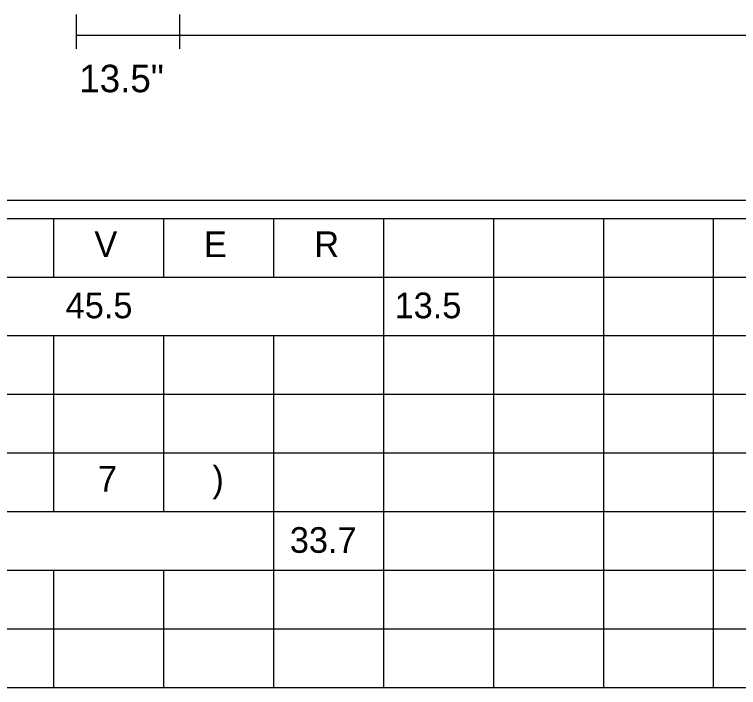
# Model space of a CAD drawing. Extents: x 10268312 to 10268471, y 2141099 to 2141204.
# Drawn here: x 10268380.92 to 10268400.67, y 2141160.23 to 2141178.59 of the extents above; entities that cross this region are included whole.
import ezdxf

# ---------------------------------------------------------------- set-up
doc = ezdxf.new("R2010")
doc.units = 0
for name, color, linetype in [('GSDims', 7, 'Continuous'), ('SumBoxLines_dp', 7, 'Continuous'), ('SumBoxLinesMin_dp', 7, 'Continuous'), ('TextLabel', 7, 'Continuous')]:
    doc.layers.add(name, color=color, linetype=linetype)

msp = doc.modelspace()

# ---------------------------------------------------------------- linework, layer by layer
at = {"layer": 'GSDims'}
for p, q in [((10268382.605, 2141178.591), (10268382.605, 2141177.653)), ((10268385.418, 2141178.591), (10268385.418, 2141177.653)), ((10268385.418, 2141178.591), (10268385.418, 2141177.653)), ((10268382.605, 2141178.028), (10268385.418, 2141178.028)), ((10268385.418, 2141178.028), (10268427.293, 2141178.028))]:
    msp.add_line(p, q, dxfattribs=at)
at = {"layer": 'SumBoxLines_dp'}
for p, q in [((10268341.73, 2141173.528), (10268470.98, 2141173.528)), ((10268318.48, 2141173.028), (10268470.98, 2141173.028)), ((10268381.98, 2141173.028), (10268381.98, 2141171.428)), ((10268384.98, 2141173.028), (10268384.98, 2141171.428)), ((10268387.98, 2141173.028), (10268387.98, 2141171.428)), ((10268390.98, 2141173.028), (10268390.98, 2141170.642)), ((10268393.98, 2141173.028), (10268393.98, 2141160.228)), ((10268396.98, 2141173.028), (10268396.98, 2141163.428)), ((10268399.98, 2141173.028), (10268399.98, 2141160.228)), ((10268390.98, 2141170.642), (10268390.98, 2141160.228)), ((10268318.48, 2141169.828), (10268470.98, 2141169.828)), ((10268381.98, 2141169.828), (10268381.98, 2141165.028)), ((10268384.98, 2141169.828), (10268384.98, 2141165.028)), ((10268387.98, 2141169.828), (10268387.98, 2141160.228)), ((10268318.48, 2141166.628), (10268470.98, 2141166.628)), ((10268318.48, 2141163.428), (10268470.98, 2141163.428)), ((10268381.98, 2141163.428), (10268381.98, 2141160.228)), ((10268384.98, 2141163.428), (10268384.98, 2141160.228)), ((10268396.98, 2141163.428), (10268396.98, 2141160.228)), ((10268318.48, 2141160.228), (10268470.98, 2141160.228))]:
    msp.add_line(p, q, dxfattribs=at)
at = {"layer": 'SumBoxLinesMin_dp'}
for p, q in [((10268318.48, 2141171.428), (10268470.98, 2141171.428)), ((10268318.48, 2141168.228), (10268470.98, 2141168.228)), ((10268318.48, 2141165.028), (10268470.98, 2141165.028)), ((10268318.48, 2141161.828), (10268470.98, 2141161.828))]:
    msp.add_line(p, q, dxfattribs=at)

# ---------------------------------------------------------------- texts
at = {"layer": 'GSDims'}
msp.add_text('13.5"', height=0.75, dxfattribs=at).set_placement((10268382.686, 2141176.47))
at = {"layer": 'TextLabel'}
for s, p in [('V', (10268383.099, 2141171.973)), ('E', (10268386.085, 2141171.973)), ('R', (10268389.097, 2141171.973)), ('45.5', (10268382.315, 2141170.303)), ('13.5', (10268391.286, 2141170.303)), ('7', (10268383.197, 2141165.573)), (')', (10268386.317, 2141165.573)), ('33.7', (10268388.43, 2141163.903))]:
    msp.add_text(s, height=0.7, dxfattribs=at).set_placement(p)

doc.saveas('drawing.dxf')
